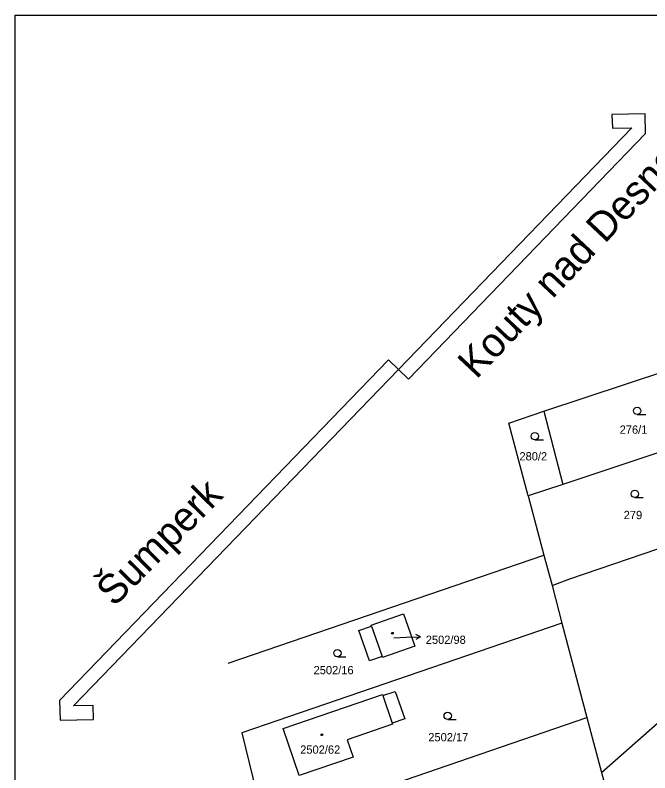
# Model space of a CAD drawing. Extents: x -558358 to -557517, y -1073786 to -1073189.
# Drawn here: x -558357.5 to -558227.2, y -1073345.8 to -1073190.1 of the extents above; entities that cross this region are included whole.
import ezdxf

# ---------------------------------------------------------------- set-up
doc = ezdxf.new("R2010")
doc.units = 0
for name, color, linetype in [('Hranice parcel', 7, 'Continuous'), ('Parcelní čísla', 7, 'Continuous'), ('Pop  PČ popisy', 7, 'Continuous'), ('Vnitřní kresba', 7, 'Continuous'), ('Vrstva 1', 7, 'Continuous'), ('Značky budov', 7, 'Continuous'), ('Značky kultur', 7, 'Continuous')]:
    doc.layers.add(name, color=color, linetype=linetype)

msp = doc.modelspace()

# ---------------------------------------------------------------- linework, layer by layer
at = {"layer": 'Hranice parcel'}
for p, q in [((-558248.97, -1073271.5), (-558221.22, -1073262.24)), ((-558256.16, -1073273.9), (-558248.97, -1073271.5)), ((-558248.97, -1073271.5), (-558245.1, -1073286.51)), ((-558254.1, -1073281.66), (-558256.16, -1073273.9)), ((-558211.74, -1073275.38), (-558245.1, -1073286.51)), ((-558252.2, -1073288.86), (-558254.1, -1073281.66)), ((-558245.1, -1073286.51), (-558252.2, -1073288.86)), ((-558252.2, -1073288.86), (-558248.97, -1073301.04)), ((-558313.8, -1073323.28), (-558248.97, -1073301.04)), ((-558248.97, -1073301.04), (-558247.31, -1073307.29)), ((-558247.31, -1073307.29), (-558245.27, -1073315.03)), ((-558245.27, -1073315.03), (-558311.02, -1073337.58)), ((-558245.27, -1073315.03), (-558240.15, -1073334.41)), ((-558305.76, -1073356.92), (-558240.15, -1073334.41)), ((-558240.15, -1073334.41), (-558237.16, -1073345.74)), ((-558237.16, -1073345.74), (-558235.73, -1073350.87))]:
    msp.add_line(p, q, dxfattribs=at)
for points in [[(-558247.31, -1073307.29), (-558243.66, -1073305.93), (-558204.33, -1073292.51)], [(-558237.16, -1073345.74), (-558202.67, -1073315.29), (-558195.58, -1073320.33), (-558174.53, -1073305.05)], [(-558275.45, -1073319.73), (-558282.1, -1073322.07), (-558282.17, -1073321.87), (-558284.8, -1073322.78), (-558286.97, -1073316.53), (-558284.37, -1073315.62), (-558284.44, -1073315.41), (-558277.79, -1073313.08), (-558275.45, -1073319.73)], [(-558302.49, -1073336.69), (-558282.13, -1073329.71), (-558282.06, -1073329.92), (-558279.49, -1073329.04), (-558277.55, -1073334.7), (-558280.12, -1073335.56), (-558280.04, -1073335.79), (-558289.36, -1073338.99), (-558288.15, -1073342.54), (-558299.21, -1073346.34), (-558302.49, -1073336.69)], [(-558311.02, -1073337.58), (-558307.96, -1073349.92), (-558305.76, -1073356.92)]]:
    msp.add_lwpolyline(points, dxfattribs=at)
at = {"layer": 'Pop  PČ popisy'}
for p, q in [((-558279.76, -1073318.04), (-558277.28, -1073317.94)), ((-558277.28, -1073317.94), (-558274.28, -1073317.83)), ((-558274.28, -1073317.83), (-558275.3, -1073317.37)), ((-558274.28, -1073317.83), (-558275.26, -1073318.37))]:
    msp.add_line(p, q, dxfattribs=at)
at = {"layer": 'Vnitřní kresba'}
for p, q in [((-558284.37, -1073315.62), (-558282.17, -1073321.87)), ((-558282.06, -1073329.92), (-558280.12, -1073335.56))]:
    msp.add_line(p, q, dxfattribs=at)
at = {"layer": 'Vrstva 1'}
for p, q in [((-558357.53, -1073784.09), (-558357.53, -1073190.09)), ((-558357.53, -1073190.09), (-557516.53, -1073190.09)), ((-558228.16, -1073210.39), (-558235.01, -1073210.51)), ((-558235.01, -1073210.51), (-558234.9, -1073213.34)), ((-558228.09, -1073214.39), (-558228.16, -1073210.39)), ((-558230.95, -1073213.27), (-558278.82, -1073262.89)), ((-558234.9, -1073213.34), (-558230.95, -1073213.27)), ((-558276.78, -1073264.86), (-558228.09, -1073214.39)), ((-558280.86, -1073260.92), (-558348.4, -1073330.92)), ((-558278.82, -1073262.89), (-558280.86, -1073260.92)), ((-558345.54, -1073332.05), (-558278.82, -1073262.89)), ((-558278.82, -1073262.89), (-558276.78, -1073264.86)), ((-558348.4, -1073330.92), (-558348.32, -1073334.93)), ((-558341.53, -1073331.97), (-558345.54, -1073332.05)), ((-558341.48, -1073334.81), (-558341.53, -1073331.97)), ((-558348.32, -1073334.93), (-558341.48, -1073334.81))]:
    msp.add_line(p, q, dxfattribs=at)
at = {"layer": 'Značky budov'}
for centre in [(-558280.08, -1073317.09), (-558294.55, -1073337.97)]:
    msp.add_circle(centre, 0.175, dxfattribs=at)
at = {"layer": 'Značky kultur'}
for p, q in [((-558229.81, -1073272.15), (-558228.06, -1073272.15)), ((-558250.84, -1073277.37), (-558249.09, -1073277.37)), ((-558230.31, -1073289.22), (-558228.56, -1073289.22)), ((-558291.38, -1073321.96), (-558289.63, -1073321.96)), ((-558268.73, -1073334.82), (-558266.98, -1073334.82))]:
    msp.add_line(p, q, dxfattribs=at)
for centre in [(-558229.81, -1073271.4), (-558250.84, -1073276.62), (-558230.31, -1073288.47), (-558291.38, -1073321.21), (-558268.73, -1073334.07)]:
    msp.add_circle(centre, 0.75, dxfattribs=at)

# ---------------------------------------------------------------- texts
at = {"layer": 'Parcelní čísla'}
for s, p in [('276/1', (-558233.42, -1073276.11)), ('280/2', (-558254, -1073281.59)), ('279', (-558232.59, -1073293.65)), ('2502/98', (-558273.23, -1073319.29)), ('2502/16', (-558296.26, -1073325.53)), ('2502/17', (-558272.71, -1073339.31)), ('2502/62', (-558299.01, -1073341.86))]:
    msp.add_text(s, height=1.7, dxfattribs=at).set_placement(p)
at = {"layer": 'Vrstva 1'}
for s, rotation, p in [('Kouty nad Desnou', 46.6457, (-558262.82, -1073265.06)), ('Šumperk', 45.2335, (-558337.2, -1073311.84))]:
    msp.add_text(s, height=6, rotation=rotation, dxfattribs=at).set_placement(p)

doc.saveas('drawing.dxf')
